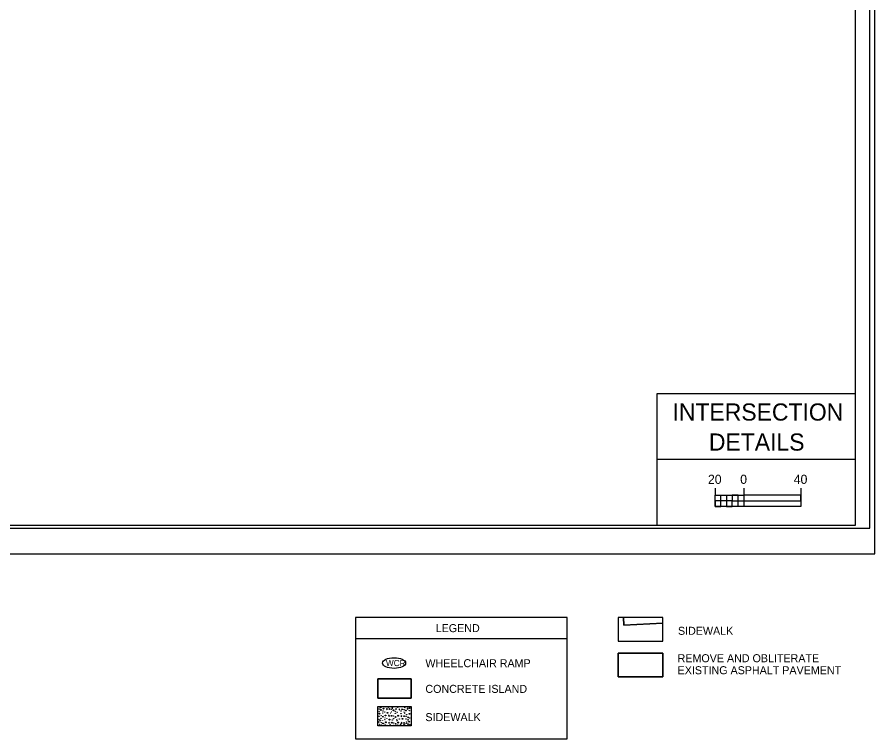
# Model space of a CAD drawing. Extents: x 2431000 to 2534000, y 645879 to 714000.
# Drawn here: x 2465774 to 2466524, y 661112 to 661743 of the extents above; entities that cross this region are included whole.
import ezdxf

# ---------------------------------------------------------------- set-up
doc = ezdxf.new("R2010")
doc.units = 0
for name, color, linetype in [('Default', 7, 'Continuous'), ('KHA_LOGO', 7, 'Continuous'), ('Level 25', 7, 'Continuous'), ('Level 57', 7, 'Continuous'), ('Level 62', 7, 'Continuous'), ('Old_Level_2', 7, 'Continuous'), ('Prop Dimension', 7, 'Continuous'), ('Prop Terminator CELL', 7, 'Continuous'), ('Scratch_Level_1', 7, 'Continuous'), ('Sheet DOT Grid CELL', 7, 'Continuous'), ('Sheet Profile CELL', 7, 'Continuous'), ('Sheet Title Data Points CELL', 7, 'Continuous')]:
    doc.layers.add(name, color=color, linetype=linetype)

msp = doc.modelspace()

# ---------------------------------------------------------------- linework, layer by layer
at = {"layer": 'KHA_LOGO'}
msp.add_line((2466070.13, 661199.49), (2466255.18, 661199.49), dxfattribs=at)
for points in [[(2466507.2, 661413.32), (2466333.64, 661413.27), (2466333.65, 661355.84)], [(2466507.22, 661355.89), (2466333.65, 661355.84), (2466333.67, 661298.4)]]:
    msp.add_lwpolyline(points, dxfattribs=at)
msp.add_lwpolyline([(2466255.18, 661217.81), (2466070.13, 661217.81), (2466070.13, 661111.71), (2466255.18, 661111.71)], close=True, dxfattribs=at)
at = {"layer": 'Level 25'}
msp.add_lwpolyline([(2466299.68, 661186.73), (2466299.68, 661165.96), (2466338.84, 661165.96), (2466338.84, 661186.73), (2466299.68, 661186.73)], dxfattribs=at)
at = {"layer": 'Level 57'}
msp.add_ellipse((2466103.73, 661177.94), major_axis=(10.09, 0), ratio=0.462467, dxfattribs=at)
at = {"layer": 'Level 62'}
msp.add_lwpolyline([(2466299.68, 661217.81), (2466299.68, 661197.04), (2466338.84, 661197.04), (2466338.84, 661217.81), (2466299.68, 661217.81)], dxfattribs=at)
for points in [[(2466299.68, 661186.73), (2466338.84, 661186.73), (2466338.84, 661165.96), (2466299.68, 661165.96)], [(2466089.55, 661164.11), (2466118.74, 661164.11), (2466118.74, 661147.27), (2466089.55, 661147.27)], [(2466089.55, 661139.89), (2466118.74, 661139.89), (2466118.74, 661123.05), (2466089.55, 661123.05)]]:
    msp.add_lwpolyline(points, close=True, dxfattribs=at)
at = {"layer": 'Old_Level_2'}
msp.add_lwpolyline([(2466507.23, 662348.46), (2465007.23, 662348.46), (2465007.23, 661298.46), (2466507.23, 661298.46)], close=True, dxfattribs=at)
at = {"layer": 'Prop Dimension'}
msp.add_lwpolyline([(2464840.73, 661273.46), (2466524.23, 661273.46), (2466524.23, 662373.46), (2464840.73, 662373.46)], close=True, dxfattribs=at)
at = {"layer": 'Prop Terminator CELL'}
msp.add_lwpolyline([(2464853.73, 661295.96), (2466519.73, 661295.96), (2466519.73, 662350.96), (2464853.73, 662350.96)], close=True, dxfattribs=at)
at = {"layer": 'Scratch_Level_1'}
for p, q in [((2466304.82, 661211.21), (2466304.48, 661217.81)), ((2466338.84, 661217.81), (2466304.48, 661217.81)), ((2466304.48, 661217.81), (2466304.82, 661211.21)), ((2466338.84, 661212.91), (2466304.82, 661211.21)), ((2466304.82, 661211.21), (2466338.84, 661212.91)), ((2466338.84, 661212.91), (2466338.84, 661217.81))]:
    msp.add_line(p, q, dxfattribs=at)
msp.add_lwpolyline([(2466304.48, 661217.81), (2466299.68, 661217.81), (2466299.68, 661197.04), (2466338.84, 661197.04), (2466338.84, 661212.91)], dxfattribs=at)
at = {"layer": 'Sheet Profile CELL'}
for p, q in [((2466384.56, 661330.93), (2466384.56, 661324.68)), ((2466409.56, 661330.93), (2466409.56, 661324.68))]:
    msp.add_line(p, q, dxfattribs=at)
msp.add_lwpolyline([(2466459.56, 661330.93), (2466459.56, 661314.68), (2466384.56, 661314.68), (2466384.56, 661324.68), (2466409.56, 661324.68)], dxfattribs=at)
for points in [[(2466394.56, 661319.68), (2466389.56, 661319.68), (2466389.56, 661324.68), (2466394.56, 661324.68)], [(2466404.56, 661324.68), (2466399.56, 661324.68), (2466399.56, 661319.68), (2466404.56, 661319.68)], [(2466459.56, 661324.68), (2466409.56, 661324.68), (2466409.56, 661319.68), (2466459.56, 661319.68)], [(2466389.56, 661319.68), (2466384.56, 661319.68), (2466384.56, 661314.68), (2466389.56, 661314.68)], [(2466399.56, 661319.68), (2466394.56, 661319.68), (2466394.56, 661314.68), (2466399.56, 661314.68)], [(2466409.56, 661314.68), (2466404.56, 661314.68), (2466404.56, 661319.68), (2466409.56, 661319.68)]]:
    msp.add_lwpolyline(points, close=True, dxfattribs=at)
at = {"layer": 'Sheet Title Data Points CELL'}
msp.add_lwpolyline([(2466089.55, 661164.11), (2466089.55, 661147.27), (2466118.74, 661147.27), (2466118.74, 661164.11), (2466089.55, 661164.11)], dxfattribs=at)
for points in [[(2466097.89, 661137.65), (2466097.14, 661138.25), (2466097.32, 661137.22)], [(2466102.54, 661138.53), (2466101.79, 661139.13), (2466101.97, 661138.1)], [(2466108.82, 661137.36), (2466108.07, 661137.96), (2466108.25, 661136.93)], [(2466115.97, 661137.93), (2466115.22, 661138.53), (2466115.4, 661137.5)], [(2466091.99, 661127.71), (2466091.25, 661128.31), (2466091.42, 661127.28)], [(2466099.69, 661131.76), (2466098.94, 661132.36), (2466099.12, 661131.33)], [(2466106.59, 661127.87), (2466105.84, 661128.47), (2466106.01, 661127.44)], [(2466110.62, 661131.47), (2466109.88, 661132.07), (2466110.05, 661131.04)], [(2466116.41, 661128.43), (2466115.66, 661129.03), (2466115.84, 661128)], [(2466099.85, 661125.74), (2466099.1, 661126.34), (2466099.28, 661125.31)], [(2466109.95, 661123.94), (2466109.21, 661124.54), (2466109.38, 661123.51)], [(2466110.78, 661125.46), (2466110.04, 661126.06), (2466110.21, 661125.03)]]:
    msp.add_lwpolyline(points, close=True, dxfattribs=at)
for centre, radius in [((2466090.57, 661137.75), 0.131), ((2466090.57, 661135.58), 0.131), ((2466091.78, 661139.06), 0.356), ((2466092.25, 661136.97), 0.356), ((2466093.98, 661135.96), 0.131), ((2466094.5, 661138.09), 0.356), ((2466095.73, 661139.5), 0.131), ((2466098.7, 661139.34), 0.131), ((2466099.75, 661137.77), 0.356), ((2466101.5, 661137.46), 0.131), ((2466101.5, 661135.3), 0.131), ((2466103.18, 661136.69), 0.356), ((2466104.91, 661135.67), 0.131), ((2466105.44, 661137.8), 0.356), ((2466106.96, 661139.34), 0.131), ((2466109.76, 661135.98), 0.131), ((2466110.69, 661137.48), 0.356), ((2466112.44, 661137.18), 0.131), ((2466113.25, 661139.06), 0.131), ((2466114.12, 661136.4), 0.356), ((2466117.19, 661138.61), 0.356), ((2466117.06, 661136.42), 0.131), ((2466090.68, 661131.49), 0.131), ((2466090.68, 661128.56), 0.131), ((2466091.09, 661133.72), 0.356), ((2466092.37, 661131.86), 0.131), ((2466092.38, 661129.69), 0.131), ((2466094.05, 661131.08), 0.356), ((2466093.88, 661134.32), 0.131), ((2466095.6, 661135.28), 0.131), ((2466095.68, 661128.43), 0.131), ((2466095.78, 661130.07), 0.131), ((2466096.31, 661132.19), 0.356), ((2466097.41, 661129.38), 0.131), ((2466097.98, 661134.42), 0.356), ((2466099.78, 661128.53), 0.356), ((2466100.42, 661134.15), 0.131), ((2466101.56, 661131.88), 0.356), ((2466102.22, 661128.26), 0.131), ((2466103.31, 661131.57), 0.131), ((2466103.31, 661129.4), 0.131), ((2466104.99, 661130.79), 0.356), ((2466104.87, 661134.05), 0.131), ((2466106.53, 661134.99), 0.131), ((2466106.72, 661129.78), 0.131), ((2466107.24, 661131.91), 0.356), ((2466108.34, 661129.09), 0.131), ((2466109.76, 661133.73), 0.131), ((2466111.14, 661129.23), 0.356), ((2466112.49, 661131.59), 0.356), ((2466112.44, 661135.01), 0.131), ((2466113.13, 661134.17), 0.131), ((2466114.24, 661131.28), 0.131), ((2466114.24, 661129.11), 0.131), ((2466114.81, 661132.77), 0.131), ((2466115.92, 661130.51), 0.356), ((2466117.15, 661133.6), 0.356), ((2466117.46, 661129.96), 0.131), ((2466090.21, 661126.43), 0.356), ((2466090.96, 661124.35), 0.131), ((2466092.53, 661125.84), 0.131), ((2466092.54, 661123.68), 0.131), ((2466093.61, 661127.56), 0.131), ((2466094.21, 661125.07), 0.356), ((2466095.94, 661124.06), 0.131), ((2466096.47, 661126.18), 0.356), ((2466097.57, 661123.37), 0.131), ((2466100.27, 661124.22), 0.131), ((2466101.72, 661125.87), 0.356), ((2466103.47, 661125.56), 0.131), ((2466103.47, 661123.39), 0.131), ((2466105.15, 661124.78), 0.356), ((2466106.88, 661123.77), 0.131), ((2466107.4, 661125.89), 0.356), ((2466112.54, 661123.9), 0.356), ((2466112.65, 661125.58), 0.356), ((2466114.4, 661125.27), 0.131), ((2466114.81, 661126.44), 0.131), ((2466116.08, 661124.49), 0.356), ((2466117.03, 661126.71), 0.356), ((2466117.62, 661124.07), 0.131)]:
    msp.add_circle(centre, radius, dxfattribs=at)

# ---------------------------------------------------------------- texts
at = {"layer": 'Default'}
for s, p in [('LEGEND', (2466140.16, 661204.98)), ('REMOVE AND OBLITERATE', (2466351.73, 661178.68)), ('EXISTING ASPHALT PAVEMENT', (2466351.73, 661168.18))]:
    msp.add_text(s, height=7, dxfattribs=at).set_placement(p)
for s, rotation, p in [('SIDEWALK', 0.01753, (2466352.04, 661202.64)), ('WHEELCHAIR RAMP', 359.99994, (2466131.14, 661174.33)), ('CONCRETE ISLAND', 359.99994, (2466131.14, 661151.88)), ('SIDEWALK', 359.99994, (2466131.14, 661127.19))]:
    msp.add_text(s, height=7, rotation=rotation, dxfattribs=at).set_placement(p)
at = {"layer": 'Level 57'}
msp.add_text('WCR', height=5.4, dxfattribs=at).set_placement((2466096.6, 661175.28))
at = {"layer": 'Sheet DOT Grid CELL'}
for s, p in [('INTERSECTION', (2466347.28, 661389.91)), ('DETAILS', (2466379.1, 661363.66))]:
    msp.add_text(s, height=15, rotation=360, dxfattribs=at).set_placement(p)
at = {"layer": 'Sheet Profile CELL'}
for s, p in [('20', (2466378.28, 661334.6)), ('0', (2466406.48, 661334.6)), ('40', (2466453.32, 661334.6))]:
    msp.add_text(s, height=8, dxfattribs=at).set_placement(p)

doc.saveas('drawing.dxf')
